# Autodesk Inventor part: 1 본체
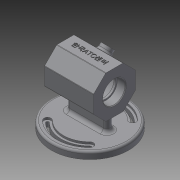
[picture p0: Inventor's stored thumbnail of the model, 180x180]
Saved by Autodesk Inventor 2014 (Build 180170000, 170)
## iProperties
Created: 2017-06
Part Number: 1 본체
Material: Generic
Document SubType Name: Modeling
Designer: Administrator
Density: 1 g/cm^3
Appearance: Default
Author: Administrator
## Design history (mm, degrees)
sketch "스케치1"
  geometry: C1 r 55 at (0, 0); 1 further point
  constraints: 1 centre point, 1 coincident
  dimensions: "d0" = 110 diameter of C1
extrude "돌출1" new body sketch "스케치1" distance "d2" = 7; taper "d3" = 0 deg
sketch "스케치2"
  geometry: L1 (0, 70.091)-(0, -70.669); L2 (-66.722, 0)-(72.691, 0); L3 (-64.441, 64.441)-(59.225, -59.225); L4 (60.185, 60.185)-(-55.495, -55.495); C1 r 55 at (0, 0) reference; A1 r 43 centre (0, 0) between (-30.406, -30.406) and (30.406, -30.406); A2 r 5 centre (-30.406, -30.406) between (-26.87, -26.87) and (-33.941, -33.941); A3 r 5 centre (30.406, -30.406) between (33.941, -33.941) and (26.87, -26.87); A4 r 38 centre (0, 0) between (-26.87, -26.87) and (26.87, -26.87); A5 r 48 centre (0, 0) between (-33.941, -33.941) and (33.941, -33.941); A6 r 2 centre (30.406, -30.406) between (31.82, -31.82) and (28.991, -28.991); A7 r 45 centre (0, 0) between (-31.82, -31.82) and (31.82, -31.82); A8 r 2 centre (-30.406, -30.406) between (-28.991, -28.991) and (-31.82, -31.82); A9 r 41 centre (0, 0) between (-28.991, -28.991) and (28.991, -28.991); A10 r 38 centre (0, 0) between (26.87, 26.87) and (-26.87, 26.87); A11 r 5 centre (30.406, 30.406) between (26.87, 26.87) and (33.941, 33.941); A12 r 41 centre (0, 0) between (28.991, 28.991) and (-28.991, 28.991); A13 r 45 centre (0, 0) between (31.82, 31.82) and (-31.82, 31.82); A14 r 48 centre (0, 0) between (33.941, 33.941) and (-33.941, 33.941); A15 r 2 centre (30.406, 30.406) between (28.991, 28.991) and (31.82, 31.82); A16 r 5 centre (-30.406, 30.406) between (-33.941, 33.941) and (-26.87, 26.87); A17 r 2 centre (-30.406, 30.406) between (-31.82, 31.82) and (-28.991, 28.991); 1 further point
  constraints: 34 point on circle, 17 centre point, 10 symmetric about line, 8 end point, 7 point on line, 3 coincident, 1 midpoint, 1 perpendicular, 1 vertical, 11 other
  dimensions: "d7" = 45 deg angle of L1 L3; "d8" = 45 deg angle of L1 L4; "d9" = 10 diameter of A3; "d12" = 10 diameter of A2; "d13" = 2 radius of A6
extrude "돌출2" cut sketch "스케치2" distance "d14" = 7; taper "d15" = 0 deg
sketch "스케치3"
  geometry: C1 r 55 at (0, 0) reference; C2 r 55 at (0, 0); A1 r 41 centre (0, 0) between (-28.991, -28.991) and (28.991, -28.991) reference; A2 r 2 centre (30.406, -30.406) between (31.82, -31.82) and (28.991, -28.991) reference; A3 r 45 centre (0, 0) between (-31.82, -31.82) and (31.82, -31.82) reference; A4 r 2 centre (-30.406, -30.406) between (-28.991, -28.991) and (-31.82, -31.82) reference; A5 r 2 centre (30.406, 30.406) between (28.991, 28.991) and (31.82, 31.82) reference; A6 r 41 centre (0, 0) between (28.991, 28.991) and (-28.991, 28.991) reference; A7 r 2 centre (-30.406, 30.406) between (-31.82, 31.82) and (-28.991, 28.991) reference; A8 r 45 centre (0, 0) between (31.82, 31.82) and (-31.82, 31.82) reference; A9 r 38 centre (0, 0) between (26.87, 26.87) and (-26.87, 26.87); A10 r 5 centre (30.406, 30.406) between (26.87, 26.87) and (33.941, 33.941); A11 r 48 centre (0, 0) between (33.941, 33.941) and (-33.941, 33.941); A12 r 5 centre (-30.406, 30.406) between (-33.941, 33.941) and (-26.87, 26.87); A13 r 38 centre (0, 0) between (-26.87, -26.87) and (26.87, -26.87); A14 r 5 centre (-30.406, -30.406) between (-26.87, -26.87) and (-33.941, -33.941); A15 r 48 centre (0, 0) between (-33.941, -33.941) and (33.941, -33.941); A16 r 5 centre (30.406, -30.406) between (33.941, -33.941) and (26.87, -26.87)
  constraints: 16 point on circle, 9 centre point, 1 coincident, 1 concentric, 6 other
  dimensions: "d16" = 5 radius of A12; "d17" = 5 radius of A14
extrude "돌출3" join sketch "스케치3" distance "d18" = 3; taper "d19" = 0 deg
sketch "스케치10" dims "d66" = 60
  geometry: L1 (-44.95, 62)-(50.167, 62); L2 (-55, 0)-(55, 0) reference; L3 (30, 49.574)-(12.426, 32); L4 (12.426, 32)-(-12.426, 32); L5 (-12.426, 32)-(-30, 49.574); L6 (-30, 49.574)-(-30, 74.426); L7 (-30, 74.426)-(-12.426, 92); L8 (-12.426, 92)-(12.426, 92); L9 (12.426, 92)-(30, 74.426); L10 (30, 74.426)-(30, 49.574); 5 further points
  constraints: 18 end point, 2 horizontal alignment, 2 midpoint, 1 coincident, 1 horizontal, 1 point on line, 1 vertical alignment, 19 other
  dimensions: "d65" = 62 distance between parallel lines of L2 L1
extrude "돌출7" join sketch "스케치10" stored distance "d67" = 70; taper "d68" = 0 deg
sketch "스케치11"
  geometry: L1 (-24, 0)-(24, 0); L2 (-24, 5)-(24, 5); L3 (24, -5)-(-24, -5); A1 r 48 centre (0, 0) between (-33.941, -33.941) and (33.941, -33.941) reference; A2 r 5 centre (-24, 0) between (-24, 5) and (-24, -5); A3 r 5 centre (24, 0) between (24, -5) and (24, 5); 1 further point
  constraints: 8 end point, 4 point on circle, 4 tangent, 2 centre point, 1 coincident, 1 horizontal, 1 midpoint, 1 parallel
  dimensions: "d69" = 48 distance of L1.end L1.start; "d70" = 5 radius of A3
extrude "돌출8" join sketch "스케치11" stored distance "d71" = 70; taper "d72" = 0 deg
sketch "스케치12"
  geometry: L1 (-35, 74.426)-(-35, 49.574) reference; L2 (35, 49.574)-(35, 74.426) reference; L3 (-54.155, 62)-(63.053, 62); L4 (-35, 62)-(-35, 78); L5 (-35, 78)-(-23, 78); L6 (-23, 78)-(-23, 76); L7 (-23, 76)-(-20, 76); L8 (-20, 76)-(-20, 87); L9 (-20, 87)-(20, 87); L10 (20, 87)-(20, 76); L11 (20, 76)-(23, 76); L12 (23, 76)-(23, 78); L13 (23, 78)-(35, 78); L14 (35, 78)-(35, 62); L15 (-35, 62)-(35, 62); L16 (35, 62)-(35, 78); 1 further point
  constraints: 28 end point, 7 perpendicular, 5 parallel, 2 midpoint, 2 point on line, 1 collinear
  dimensions: "d73" = 62 distance from line of point (0, 0) L3; "d74" = 32 diameter of L5 L3; "d75" = 12 distance of L4.end L5.end; "d76" = 28 diameter of L7 L3; "d77" = 3 distance of L6.end L7.end; "d78" = 40 distance of L8.end L9.end; "d79" = 50 diameter of L9 L3; "d80" = 3 distance of L10.end L11.end; "d81" = 28 diameter of L11 L3; "d82" = 32 diameter of L13 L3
revolve "회전2" sketch "스케치12" stored, may be unused: angle "d83" = 90 deg
node "작업 평면2"
sketch "스케치13"
  geometry: C1 r 8 at (35, 11.47); 1 further point
  constraints: 1 centre point, 1 vertical alignment
  dimensions: "d85" = 16 diameter of C1
extrude "돌출9" join sketch "스케치13" stored distance "d86" = 70; taper "d87" = 0 deg
sketch "스케치14"
  geometry: L1 (0, 0)-(0, 24.853) reference; L2 (70, 42.426)-(0, 42.426) reference; 2 further points
  constraints: 1 other
  dimensions: "d88" = 35 distance from line of point (35, 12.426) L1; "d89" = 30 distance from line of L2 point (35, 12.426)
feature "엠보싱1" sketch "스케치14" dims "d90" = 0.5, "d91" = 0
fillet "모깎기1" dims "d92" = 1
fillet "모깎기2" dims "d93" = 5
fillet "모깎기3" dims "d94" = 3
chamfer "모따기1" distance "d95" = 1; stored, may be unused: second distance "d96" = 2, angle "d97" = 45 deg
hole "구멍2" diameter "d100" = 8; stored, may be unused: countersink angle "d104" = 90 deg, drill point angle "d106" = 0 deg; dims "d98" = 10, "d99" = 10, "d101" = 8, "d102" = 4, "d103" = 2, "d105" = 28.25
chamfer "모따기2" distance "d107" = 1; stored, may be unused: second distance "d108" = 2, angle "d109" = 45 deg
node "솔리드1"
other parameters: "d4" = 96, "d6" = 76, "d84" = 7
